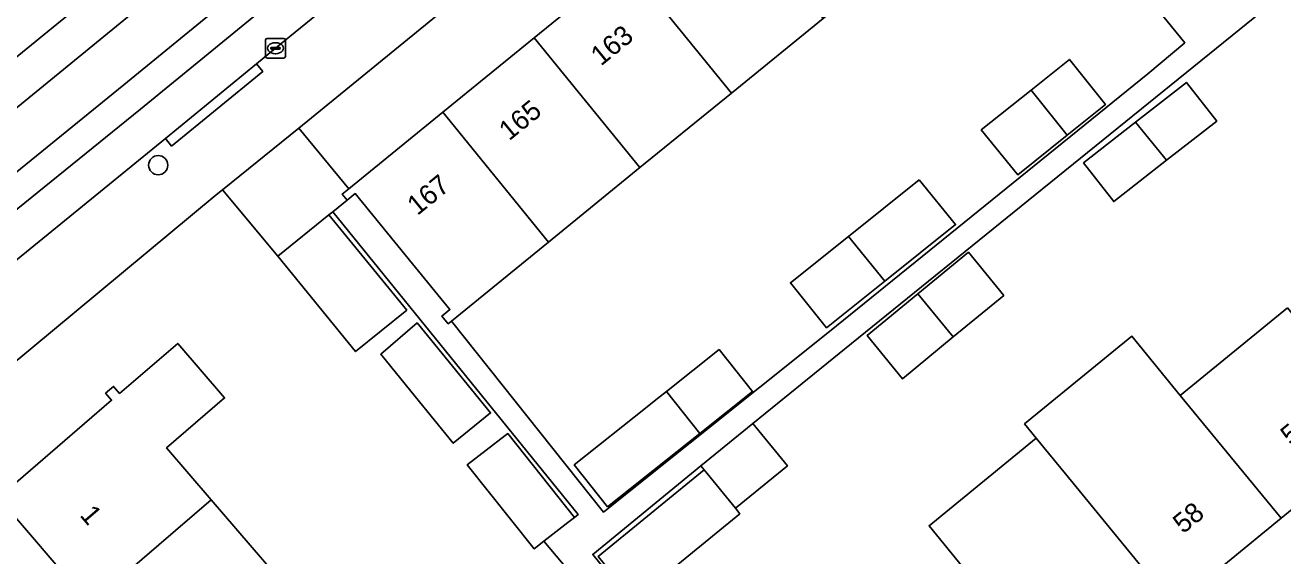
# Model space of a CAD drawing. Extents: x 162523 to 163266, y 381230 to 382050.
# Drawn here: x 162615.3 to 162679.2, y 381867.7 to 381894.7 of the extents above; entities that cross this region are included whole.
import ezdxf

# ---------------------------------------------------------------- set-up
doc = ezdxf.new("R2010")
doc.units = 0
for name, color, linetype in [('IMGEO_Boom', 7, 'Continuous'), ('IMGEO_Erf', 7, 'Continuous'), ('IMGEO_Groenvoorziening', 7, 'Continuous'), ('IMGEO_Haag', 7, 'Continuous'), ('IMGEO_Kolk', 7, 'Continuous'), ('IMGEO_Pand', 7, 'Continuous'), ('IMGEO_Pand_nummerreeks', 7, 'Continuous'), ('IMGEO_Parkeervlak_open', 7, 'Continuous'), ('IMGEO_Rijbaan_lokaal_gesloten', 7, 'Continuous'), ('IMGEO_Rijbaan_lokaal_open', 7, 'Continuous'), ('IMGEO_Rijbaan_regionaal_gesloten', 7, 'Continuous'), ('IMGEO_Voetpad_open', 7, 'Continuous')]:
    doc.layers.add(name, color=color, linetype=linetype)

msp = doc.modelspace()

# ---------------------------------------------------------------- linework, layer by layer
at = {"layer": 'IMGEO_Boom'}
msp.add_circle((162622.059, 381887.597), 0.489, dxfattribs=at)
at = {"layer": 'IMGEO_Erf'}
for points in [[(162650.468, 381901.655), (162655.119, 381905.446), (162660.154, 381909.549), (162660.363, 381909.293), (162661.029, 381909.836), (162658.271, 381913.213), (162629.198, 381889.473), (162631.746, 381886.399), (162636.515, 381890.285), (162641.166, 381894.075), (162645.817, 381897.866)], [(162672.352, 381892.247), (162674.22, 381893.818), (162669.961, 381899.078), (162667.26, 381896.876), (162663.596, 381901.373), (162660.495, 381898.846), (162655.844, 381895.056), (162651.193, 381891.266), (162646.542, 381887.476), (162641.891, 381883.686), (162636.959, 381879.667), (162644.684, 381869.964), (162649.096, 381873.476), (162656.174, 381879.145)], [(162663.887, 381889.388), (162666.416, 381891.413), (162668.361, 381892.97), (162670.196, 381890.679), (162668.251, 381889.121), (162665.741, 381887.111)], [(162705.634, 381887.408), (162708.484, 381889.327), (162706.449, 381892.03), (162706.385, 381891.977), (162700.904, 381887.488), (162695.458, 381883.027), (162690.012, 381878.567), (162684.564, 381874.105), (162679.119, 381869.645), (162673.672, 381865.184), (162668.226, 381860.724), (162662.779, 381856.263), (162657.225, 381851.715), (162659.11, 381849.371), (162659.283, 381849.513)], [(162670.614, 381885.747), (162669.08, 381887.709), (162671.725, 381889.777), (162674.313, 381891.801), (162675.848, 381889.839), (162673.304, 381887.85)], [(162660.722, 381886.854), (162662.576, 381884.577), (162658.985, 381881.701), (162656.025, 381879.331), (162654.189, 381881.623), (162657.13, 381883.978)], [(162659.881, 381876.743), (162658.079, 381878.935), (162660.665, 381881.061), (162663.227, 381883.167), (162665.03, 381880.975), (162662.464, 381878.865)], [(162635.117, 381875.835), (162633.364, 381877.987), (162635.217, 381879.581), (162637.011, 381877.379), (162638.947, 381875.004), (162637.052, 381873.46)], [(162652.256, 381876.093), (162649.582, 381873.964), (162644.892, 381870.231), (162643.198, 381872.359), (162646.901, 381875.307), (162647.352, 381875.666), (162647.439, 381875.736), (162647.888, 381876.093), (162650.562, 381878.221)]]:
    msp.add_lwpolyline(points, close=True, dxfattribs=at)
for points in [[(162693.22, 381907.888), (162678.141, 381895.414), (162666.617, 381886.082), (162657.294, 381878.532), (162652.276, 381874.469), (162654.037, 381872.318), (162651.396, 381870.156), (162651.611, 381869.873), (162646.244, 381865.476), (162644.419, 381867.704), (162649.797, 381872.109), (162649.635, 381872.306), (162644.145, 381867.808), (162650.304, 381860.178), (162652.987, 381862.376), (162654.784, 381860.182), (162657.649, 381862.525), (162663.098, 381866.981), (162661.229, 381869.262), (162666.679, 381873.719), (162666.089, 381874.439), (162671.539, 381878.897), (162673.998, 381875.896), (162679.447, 381880.352)], [(162656.106, 381851.292), (162641.659, 381868.486), (162641.157, 381868.1), (162637.76, 381872.365), (162639.696, 381873.854), (162639.819, 381873.949), (162643.216, 381869.683), (162643.398, 381869.837), (162630.931, 381885.233), (162630.737, 381885.079), (162634.685, 381880.234), (162632.091, 381878.12), (162628.143, 381882.965), (162625.328, 381886.346), (162625.011, 381886.086), (162608.447, 381872.351)], [(162614.191, 381870.91), (162619.691, 381875.644), (162619.382, 381876.003), (162619.79, 381876.353), (162620.098, 381875.995), (162623.052, 381878.537), (162625.435, 381875.769), (162622.482, 381873.226), (162624.758, 381870.581), (162629.348, 381865.247)], [(162618.592, 381865.275), (162613.633, 381871.038)]]:
    msp.add_lwpolyline(points, dxfattribs=at)
at = {"layer": 'IMGEO_Groenvoorziening'}
for points in [[(162680.739, 381946.928), (162671.529, 381939.448), (162665.643, 381934.608), (162662.907, 381932.358), (162646.842, 381919.202), (162628.275, 381903.978), (162616.901, 381894.769), (162600.282, 381881.209), (162593.659, 381875.675), (162587.814, 381870.584), (162581.631, 381865.192), (162576.654, 381860.802), (162570.541, 381855.349), (162568.79, 381853.73), (162563.048, 381848.267), (162562.147, 381847.417)], [(162562.824, 381846.988), (162573.602, 381856.338), (162582.504, 381864.006), (162588.508, 381868.991), (162589.487, 381869.827), (162603.985, 381881.713), (162607.58, 381884.559), (162623.559, 381897.652), (162657.024, 381924.879)]]:
    msp.add_lwpolyline(points, dxfattribs=at)
at = {"layer": 'IMGEO_Haag'}
for points in [[(162562.824, 381846.988), (162573.602, 381856.338), (162582.504, 381864.006), (162588.508, 381868.991), (162589.487, 381869.827), (162603.985, 381881.713), (162607.58, 381884.559), (162623.559, 381897.652), (162657.024, 381924.879), (162674.516, 381939.191), (162688.899, 381951.026), (162689.109, 381951.165), (162692.795, 381954.244), (162706.361, 381965.315), (162723.06, 381979.017), (162732.21, 381986.499)], [(162680.739, 381946.928), (162671.529, 381939.448), (162665.643, 381934.608), (162662.907, 381932.358), (162646.842, 381919.202), (162628.275, 381903.978), (162616.901, 381894.769), (162600.282, 381881.209), (162593.659, 381875.675), (162587.814, 381870.584), (162581.631, 381865.192), (162576.654, 381860.802), (162570.541, 381855.349), (162568.79, 381853.73), (162563.048, 381848.267), (162562.147, 381847.417)]]:
    msp.add_lwpolyline(points, dxfattribs=at)
at = {"layer": 'IMGEO_Kolk'}
for p, q in [((162627.519, 381893.119), (162627.519, 381893.971)), ((162627.594, 381894.045), (162628.446, 381894.045)), ((162628.007, 381893.825), (162628.032, 381893.825)), ((162628.52, 381893.971), (162628.52, 381893.119)), ((162627.778, 381893.539), (162627.778, 381893.551)), ((162628.216, 381893.502), (162627.818, 381893.502)), ((162627.821, 381893.588), (162628.219, 381893.588)), ((162628.03, 381893.265), (162628.005, 381893.265)), ((162628.262, 381893.551), (162628.262, 381893.539)), ((162628.446, 381893.045), (162627.594, 381893.045))]:
    msp.add_line(p, q, dxfattribs=at)
for points in [[(162627.519, 381893.119), (162627.519, 381893.971)], [(162627.594, 381894.045), (162628.446, 381894.045)], [(162628.52, 381893.971), (162628.52, 381893.119)], [(162628.446, 381893.045), (162627.594, 381893.045)]]:
    msp.add_lwpolyline(points, dxfattribs=at)
for centre, radius, start, end in [((162627.596, 381893.969), 0.0765, 91.55205, 178.44795), ((162627.596, 381893.969), 0.0765, 91.55205, 178.44795), ((162628.444, 381893.969), 0.0765, 1.55205, 88.44795), ((162628.444, 381893.969), 0.0765, 1.55205, 88.44795), ((162627.818, 381893.548), 0.0403, 85.87752, 175.75265), ((162627.815, 381893.538), 0.0366, 178.93798, 274.71019), ((162628.219, 381893.545), 0.043, 264.86636, 352.45326), ((162628.223, 381893.55), 0.0386, 1.73085, 96.63898), ((162627.596, 381893.121), 0.0765, 181.55205, 268.44795), ((162627.596, 381893.121), 0.0765, 181.55205, 268.44795), ((162628.444, 381893.121), 0.0765, 271.55205, 358.44795), ((162628.444, 381893.121), 0.0765, 271.55205, 358.44795)]:
    msp.add_arc(centre, radius, start, end, dxfattribs=at)
for centre, major_axis, ratio, start_param, end_param in [((162628.006, 381893.545), (-0.387, 0.002), 0.722429, 4.712389, 7.853982), ((162628.031, 381893.545), (-0.39, 0.002), 0.717154, 1.570796, 4.712389)]:
    msp.add_ellipse(centre, major_axis=major_axis, ratio=ratio, start_param=start_param, end_param=end_param, dxfattribs=at)
at = {"layer": 'IMGEO_Pand'}
for points in [[(162650.468, 381901.655), (162645.817, 381897.866), (162651.193, 381891.266), (162655.844, 381895.056)], [(162651.193, 381891.266), (162645.817, 381897.866), (162641.166, 381894.075), (162646.542, 381887.476)], [(162636.515, 381890.285), (162641.891, 381883.686), (162646.542, 381887.476), (162641.166, 381894.075)], [(162666.416, 381891.413), (162668.251, 381889.121), (162670.196, 381890.679), (162668.361, 381892.97)], [(162668.251, 381889.121), (162666.416, 381891.413), (162663.887, 381889.388), (162665.741, 381887.111)], [(162671.725, 381889.777), (162673.304, 381887.85), (162675.848, 381889.839), (162674.313, 381891.801)], [(162636.515, 381890.285), (162631.746, 381886.399), (162631.411, 381886.126), (162631.665, 381885.814), (162632.076, 381886.149), (162634.981, 381882.585), (162636.881, 381880.253), (162636.479, 381879.925), (162636.797, 381879.535), (162636.959, 381879.667), (162641.891, 381883.686)], [(162673.304, 381887.85), (162671.725, 381889.777), (162669.08, 381887.709), (162670.614, 381885.747)], [(162660.722, 381886.854), (162657.13, 381883.978), (162658.985, 381881.701), (162662.576, 381884.577)], [(162628.143, 381882.965), (162632.091, 381878.12), (162634.685, 381880.234), (162630.737, 381885.079)], [(162658.985, 381881.701), (162657.13, 381883.978), (162654.189, 381881.623), (162656.025, 381879.331)], [(162660.665, 381881.061), (162662.464, 381878.865), (162665.03, 381880.975), (162663.227, 381883.167)], [(162662.464, 381878.865), (162660.665, 381881.061), (162658.079, 381878.935), (162659.881, 381876.743)], [(162679.447, 381880.352), (162673.998, 381875.896), (162679.119, 381869.645), (162684.564, 381874.105)], [(162637.011, 381877.379), (162635.217, 381879.581), (162633.364, 381877.987), (162635.117, 381875.835), (162637.052, 381873.46), (162638.947, 381875.004)], [(162620.098, 381875.995), (162619.79, 381876.353), (162619.382, 381876.003), (162619.691, 381875.644), (162614.191, 381870.91), (162613.89, 381871.259), (162613.633, 381871.038), (162618.592, 381865.275), (162624.758, 381870.581), (162622.482, 381873.226), (162625.435, 381875.769), (162623.052, 381878.537)], [(162673.998, 381875.896), (162671.539, 381878.897), (162666.089, 381874.439), (162666.679, 381873.719), (162668.548, 381871.438), (162673.672, 381865.184), (162679.119, 381869.645)], [(162647.888, 381876.093), (162649.582, 381873.964), (162652.256, 381876.093), (162650.562, 381878.221)], [(162649.582, 381873.964), (162647.888, 381876.093), (162647.439, 381875.736), (162647.352, 381875.666), (162646.901, 381875.307), (162643.198, 381872.359), (162644.892, 381870.231)], [(162652.276, 381874.469), (162649.635, 381872.306), (162649.797, 381872.109), (162651.396, 381870.156), (162654.037, 381872.318)], [(162639.819, 381873.949), (162639.696, 381873.854), (162637.76, 381872.365), (162641.157, 381868.1), (162641.659, 381868.486), (162642.883, 381869.427), (162643.216, 381869.683)], [(162668.548, 381871.438), (162666.679, 381873.719), (162661.229, 381869.262), (162663.098, 381866.981), (162668.226, 381860.724), (162673.672, 381865.184)], [(162651.396, 381870.156), (162649.797, 381872.109), (162644.419, 381867.704), (162646.244, 381865.476), (162651.611, 381869.873)], [(162623.185, 381859.939), (162629.348, 381865.247), (162624.758, 381870.581), (162618.592, 381865.275)]]:
    msp.add_lwpolyline(points, close=True, dxfattribs=at)
at = {"layer": 'IMGEO_Parkeervlak_open'}
msp.add_lwpolyline([(162734.674, 381983.196), (162734.879, 381983.414), (162719.334, 381970.721), (162660.667, 381922.782), (162621.159, 381890.444), (162606.537, 381878.623), (162607.835, 381877.056), (162611.312, 381879.905), (162622.426, 381888.955), (162627.054, 381892.753), (162628.02, 381893.546), (162645.534, 381907.811), (162660.687, 381920.23), (162678.17, 381934.546), (162692.562, 381946.284), (162710.873, 381961.232), (162726.796, 381974.271), (162733.168, 381979.496), (162733.544, 381980.135), (162733.629, 381980.885)], dxfattribs=at)
msp.add_lwpolyline([(162631.665, 381885.814), (162631.411, 381886.126), (162631.746, 381886.399), (162629.198, 381889.473), (162625.328, 381886.346), (162628.143, 381882.965), (162630.737, 381885.079), (162630.931, 381885.233)], close=True, dxfattribs=at)
at = {"layer": 'IMGEO_Rijbaan_lokaal_gesloten'}
msp.add_lwpolyline([(162605.631, 381879.753), (162606.537, 381878.623), (162621.159, 381890.444), (162660.667, 381922.782), (162719.334, 381970.721), (162734.879, 381983.414), (162741.157, 381987.731), (162741.237, 381987.785), (162739.98, 381989.555), (162730.755, 381982.044), (162718.174, 381971.736), (162694.41, 381952.302), (162690.659, 381949.234), (162620.312, 381891.687)], close=True, dxfattribs=at)
at = {"layer": 'IMGEO_Rijbaan_lokaal_open'}
msp.add_lwpolyline([(162603.985, 381881.713), (162605.631, 381879.753), (162620.312, 381891.687), (162690.659, 381949.234), (162689.109, 381951.165), (162688.899, 381951.026), (162674.516, 381939.191), (162657.024, 381924.879), (162623.559, 381897.652), (162607.58, 381884.559)], close=True, dxfattribs=at)
at = {"layer": 'IMGEO_Rijbaan_regionaal_gesloten'}
msp.add_lwpolyline([(162542.033, 381827.792), (162551.188, 381837.076), (162562.147, 381847.417), (162563.048, 381848.267), (162568.79, 381853.73), (162570.541, 381855.349), (162576.654, 381860.802), (162581.631, 381865.192), (162587.814, 381870.584), (162593.659, 381875.675), (162600.282, 381881.209), (162616.901, 381894.769), (162628.275, 381903.978), (162646.842, 381919.202), (162662.907, 381932.358), (162665.643, 381934.608), (162671.529, 381939.448), (162680.739, 381946.928)], dxfattribs=at)
at = {"layer": 'IMGEO_Voetpad_open'}
for points in [[(162733.629, 381980.885), (162733.544, 381980.135), (162733.168, 381979.496), (162726.796, 381974.271), (162710.873, 381961.232), (162692.562, 381946.284), (162678.17, 381934.546), (162660.687, 381920.23), (162645.534, 381907.811), (162628.02, 381893.546), (162627.054, 381892.753), (162627.371, 381892.367), (162622.743, 381888.569), (162622.426, 381888.955), (162611.312, 381879.905), (162607.835, 381877.056), (162605.991, 381875.483)], [(162604.976, 381869.467), (162608.447, 381872.351), (162625.011, 381886.086), (162625.328, 381886.346), (162629.198, 381889.473), (162658.271, 381913.213), (162659.562, 381914.267), (162689.864, 381939.01)], [(162669.961, 381899.078), (162674.22, 381893.818), (162672.352, 381892.247), (162656.174, 381879.145), (162649.096, 381873.476), (162644.684, 381869.964), (162636.959, 381879.667), (162636.797, 381879.535), (162636.479, 381879.925), (162636.881, 381880.253), (162634.981, 381882.585), (162632.076, 381886.149), (162631.665, 381885.814), (162630.931, 381885.233), (162643.398, 381869.837), (162643.216, 381869.683), (162642.883, 381869.427), (162641.659, 381868.486), (162656.106, 381851.292)], [(162650.304, 381860.178), (162644.145, 381867.808), (162649.635, 381872.306), (162652.276, 381874.469), (162657.294, 381878.532), (162666.617, 381886.082), (162678.141, 381895.414)]]:
    msp.add_lwpolyline(points, dxfattribs=at)
msp.add_lwpolyline([(162622.426, 381888.955), (162622.743, 381888.569), (162627.371, 381892.367), (162627.054, 381892.753)], close=True, dxfattribs=at)

# ---------------------------------------------------------------- texts
at = {"layer": 'IMGEO_Pand_nummerreeks'}
for s, rotation, p in [('163', 39.17699, (162644.558, 381892.609)), ('165', 39.17699, (162639.893, 381888.807)), ('167', 39.17885, (162635.228, 381885.005)), ('56', 39.31735, (162679.61, 381873.304)), ('1', 310.71417, (162618.038, 381869.784)), ('58', 39.31636, (162674.143, 381868.827))]:
    msp.add_text(s, height=1, rotation=rotation, dxfattribs=at).set_placement(p)

doc.saveas('drawing.dxf')
